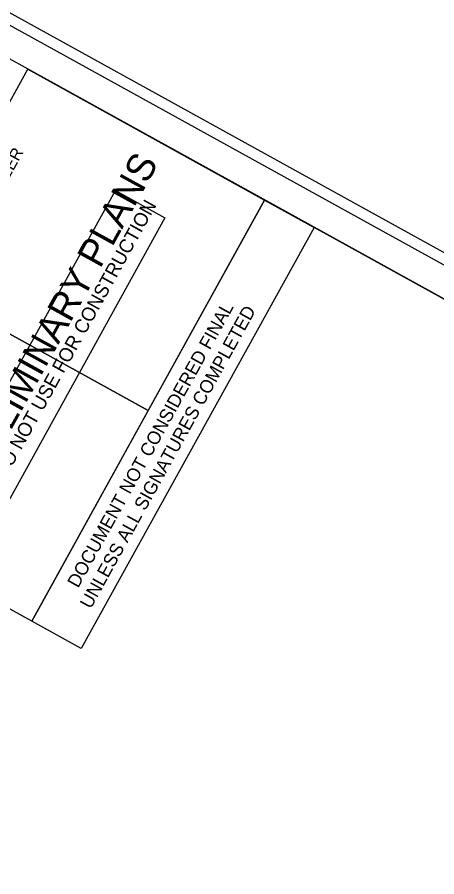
# Model space of a CAD drawing. Extents: x 2176096 to 2177873, y 76962 to 79129.
# Drawn here: x 2176952.2 to 2177126.7, y 78587.4 to 78945 of the extents above; entities that cross this region are included whole.
import ezdxf

# ---------------------------------------------------------------- set-up
doc = ezdxf.new("R2010")
doc.units = 0
for name, color, linetype in [('CTL Primary Horizontal and Vertical CELL', 7, 'Continuous'), ('CTL Primary Horizontal CELL', 7, 'Continuous'), ('CTL Primary Horizontal Cogo Comment', 7, 'Continuous'), ('CTL Primary Horizontal Cogo Number', 7, 'Continuous'), ('Exist Other Culture Sign Cogo Point CELL', 7, 'Continuous'), ('Exist Property Iron Pin Cogo Elevation', 7, 'Continuous')]:
    doc.layers.add(name, color=color, linetype=linetype)

msp = doc.modelspace()

# ---------------------------------------------------------------- linework, layer by layer
at = {"layer": 'CTL Primary Horizontal and Vertical CELL'}
msp.add_lwpolyline([(2176761.97, 78648.71), (2176276.9, 77770.96), (2176400.52, 77667.34), (2176500.72, 77583.35), (2176559.15, 77534.36), (2176927.7, 77225.43), (2177117.21, 77120.7), (2177568.3, 77936.95), (2177830.41, 78411.24), (2177842.75, 78433.56), (2177075.64, 78857.48), (2176978.88, 78682.4), (2176907.89, 78721.63), (2176842.88, 78604)], close=True, dxfattribs=at)
at = {"layer": 'CTL Primary Horizontal CELL'}
msp.add_lwpolyline([(2176927.56, 78953.61), (2176121.49, 77495.02), (2177044.95, 76984.68), (2177851.02, 78443.27)], close=True, dxfattribs=at)
at = {"layer": 'CTL Primary Horizontal Cogo Comment'}
for p, q in [((2176958.31, 78693.77), (2177055.07, 78868.85)), ((2177055.08, 78868.84), (2177075.65, 78857.47)), ((2177075.64, 78857.48), (2176978.88, 78682.4)), ((2176978.88, 78682.4), (2176958.31, 78693.77))]:
    msp.add_line(p, q, dxfattribs=at)
at = {"layer": 'CTL Primary Horizontal Cogo Number'}
msp.add_lwpolyline([(2176910.09, 78968.41), (2176095.55, 77494.5), (2177058.32, 76962.44), (2177872.85, 78436.35)], close=True, dxfattribs=at)
at = {"layer": 'Exist Other Culture Sign Cogo Point CELL'}
msp.add_line((2176908.24, 78835.75), (2177006.66, 78781.36), dxfattribs=at)
for points in [[(2176923.74, 78941.44), (2176198.21, 77628.58), (2177117.21, 77120.7), (2177842.75, 78433.56)], [(2176908.24, 78835.75), (2176956.61, 78923.27), (2177055.07, 78868.86), (2177006.7, 78781.33)], [(2176859.85, 78748.18), (2176908.24, 78835.75), (2177006.7, 78781.33), (2176958.31, 78693.77)]]:
    msp.add_lwpolyline(points, close=True, dxfattribs=at)
at = {"layer": 'Exist Property Iron Pin Cogo Elevation'}
msp.add_lwpolyline([(2176942.49, 78732.84), (2176921.92, 78744.21), (2176993.02, 78872.87), (2177013.59, 78861.5)], close=True, dxfattribs=at)

# ---------------------------------------------------------------- texts
at = {"layer": 'CTL Primary Horizontal Cogo Comment'}
for s, p in [('DOCUMENT NOT CONSIDERED FINAL', (2176977.56, 78707.2)), ('UNLESS ALL SIGNATURES COMPLETED', (2176982.81, 78698.51))]:
    msp.add_text(s, height=5.5, rotation=61.0733, dxfattribs=at).set_placement(p)
at = {"layer": 'Exist Other Culture Sign Cogo Point CELL'}
msp.add_text('ENGINEER', height=5, rotation=61.0733, dxfattribs=at).set_placement((2176938.15, 78858.35))
at = {"layer": 'Exist Property Iron Pin Cogo Elevation'}
for s, height, p in [('PRELIMINARY PLANS', 11.52, (2176934.12, 78744.89)), ('DO NOT USE FOR CONSTRUCTION', 5.76, (2176947.2, 78752.64))]:
    msp.add_text(s, height=height, rotation=61.0733, dxfattribs=at).set_placement(p)

doc.saveas('drawing.dxf')
